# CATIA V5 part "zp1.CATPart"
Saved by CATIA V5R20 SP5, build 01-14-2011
Part number: 后轮
Bounding box of the stored display mesh (mm): x -60 to 60, y -45 to 51.23, z -60 to 60
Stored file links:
  E:\180512116\zp\20190505\180512116赵克君\zp1.CATPart
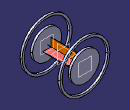
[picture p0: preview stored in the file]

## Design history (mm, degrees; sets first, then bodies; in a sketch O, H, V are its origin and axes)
Body1 (main body)
  Sketch1 on xy-plane, origin (0, 0, 0), H (1, 0, 0), V (0, 1, 0)
    line L1 (0, 51.2303) -> (0, -38.7697)
    point P1 (0, 51.2303)
    vertical: L1 V
  Plane1: type Normal, Curve Sketch1, RefPoint Sketch1.P1
  Sketch2 on Plane1, origin (0, 51.2303, 0), H (1, 0, 0), V (0, 0, 1)
    circle A1 centre (0, 0) radius 0.5
    radius A1 = 0.5
  Rib1: profile Sketch2, centre curve Sketch1
  Sketch3 on zx-plane, origin (0, 0, 0), H (-1, 0, 0), V (0, 0, 1)
    line L1 (20, 0.5) -> (20, -0.5)
    line L2 (20, -0.5) -> (-20, -0.5)
    line L3 (-20, -0.5) -> (-20, 0.5)
    line L4 (-20, 0.5) -> (20, 0.5)
    length L1 = 1
    length L4 = 40
    vertical: L1 V, L3 V
    horizontal: L2 H, L4 H
    equidistance: L1 L3 O, L2 L4 O
  Pad1: profile Sketch3, direction (0, 1, 0), length 30, mirrored extent
  Sketch4 on zx-plane, origin (0, 0, 0), H (-1, 0, 0), V (0, 0, 1)
    line L1 (0.5, 20) -> (0.5, -20)
    line L2 (0.5, -20) -> (-0.5, -20)
    line L3 (-0.5, -20) -> (-0.5, 20)
    line L4 (-0.5, 20) -> (0.5, 20)
    length L2 = 1
    length L1 = 40
    vertical: L1 V, L3 V
    horizontal: L2 H, L4 H
    equidistance: L1 L3 O, L2 L4 O
  Pad2: profile Sketch4, direction (0, 1, 0), length 30, mirrored extent
  Sketch5 on Plane1, origin (0, 51.2303, 0), H (1, 0, 0), V (0, 0, 1)
    circle A1 centre (0, 0) radius 60
    radius A1 = 60
  Pad3: profile Sketch5, direction (0, -1, 0), length 5
  Plane2: type Offset, RefPlane zx-plane, Offset 40, reversed
  Sketch6 on Plane2, origin (0, -40, 0), H (-1, 0, 0), V (0, 0, 1)
    circle A1 centre (0, 0) radius 60
    radius A1 = 60
  Pad4: profile Sketch6, direction (0, -1, 0), length 5
  Sketch7 on face of Pad3, origin (0, 51.2303, 0), H (-1, 0, 0), V (0, 0, 1)
    circle A1 centre (0, 0) radius 55
    radius A1 = 55
  Pocket1: profile Sketch7, direction (0, -1, 0), length 5
  Sketch8 on end face of Pad4, origin (0, -45, 0), H (1, 0, 0), V (0, 0, 1)
    circle A1 centre (0, 0) radius 55
    radius A1 = 55
  Pocket2: profile Sketch8, direction (0, 1, 0), length 5
  Sketch9 on Plane1, origin (0, 51.2303, 0), H (1, 0, 0), V (0, 0, 1)
    circle A1 centre (0, 0) radius 35
    radius A1 = 35
  Pad5: profile Sketch9, direction (0, -1, 0), length 5
  Sketch10 on Plane2, origin (0, -40, 0), H (-1, 0, 0), V (0, 0, 1)
    circle A1 centre (0, 0) radius 35
    radius A1 = 35
  Pad6: profile Sketch10, direction (0, -1, 0), length 5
